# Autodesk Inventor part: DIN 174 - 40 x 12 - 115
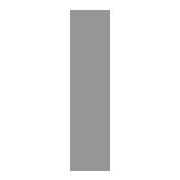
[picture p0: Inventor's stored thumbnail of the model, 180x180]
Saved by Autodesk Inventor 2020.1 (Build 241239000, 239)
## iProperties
IsCustomPart: 1
_CCFamilyMember: 175
_CCFamilyDisplayName: DIN EN 10278 - Flachstahl
_FrameMemberDoc: Frame Member File
_Version: 15.0.0
_GetPNFromCC: 1
Created: 2019-01
Part Number: DIN 174 - 40 x 12 - 115
Material: Stahl, weich
Description: Flachstahl
Document SubType Name: Modeling
Standard: DIN
Designer: lutzd
Standards Organization: DIN
Language: de-DE
Size Designation: 40 x 12
Categories: <MemberInstance><Categories><Category DisplayName="Profile" InternalName="089c4875-fa83-4c05-b084-43b9cc11f5ed" Mnemonic="GRDR"><CategoryParameter DisplayName="
Stock Number: 40 x 12
Mass: 406.353 g
Surface Area: 133.653 cm^2
Volume: 51.7647 cm^3
Density: 7.85 g/cm^3
Appearance: Semi-Polished(8)
G_L: 115,000 mm
G_W: 12,000 mm
G_H: 40,000 mm
DocNumber: ADSK-014318
Folder: .
Dimensions: 12x40x115 mm
Mass: 0,406 kg
Title: Profil-Bauteil
Author: lutzd
Revision Number: -
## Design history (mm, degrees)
node "Startebene"
node "Endebene"
sketch "Skizze"
  geometry: L1 (6, -20)-(-6, -20); L2 (-6, -20)-(-6, 20); L3 (-6, 20)-(6, 20); L4 (6, 20)-(6, -20); L5 (-6, 0)-(8, 0); L6 (0, -30)-(0, 40); L7 (0, 54)-(0, -44) reference; L8 (-9.2, 0)-(13.2, 0) reference
  constraints: 12 end point, 2 collinear, 2 parallel, 1 horizontal, 1 perpendicular
  dimensions: "d0" = 40 distance between parallel lines of L3 L1 (= G_W); "d1" = 12 distance between parallel lines of L4 L2 (= G_H); "d4" = 6 distance between parallel lines of L6 L4 (= 0.5 x d1); "d5" = 20 distance between parallel lines of L5 L3 (= 0.5 x d0)
extrude "Körper" new body sketch "Skizze" stored distance "d2" = 115 (= G_L); taper "d3" = 0 deg
node "Driven Length"
  sketch "Sketch3"
    geometry: L1 (0, 0)-(10, 0) reference
    constraints: 2 end point, 1 horizontal
  workplane "Work Plane3"
  sketch "Sketch4"
    geometry: L1 (-2, 0)-(12, 0) reference; L2 (-2, 115)-(12, 115) reference
    dimensions: "d9" = 115 distance between parallel lines of L1 L2 (derived)
sketch "Skizze5"
  geometry: L1 (16.5, -20)-(98.5, -20); L2 (0, 0)-(115, 0) reference; L3 (0, -40)-(0, 0) reference; 6 further points
  constraints: 3 midpoint, 2 coincident, 2 end point, 1 horizontal, 1 horizontal alignment, 1 vertical alignment
  dimensions: "d10" = 82 distance of L1.start L1.end
hole "Bohrung1" sketch "Skizze5" at (16.5, -20), (98.5, -20) diameter "d12" = 13.5; stored, may be unused: countersink angle "d16" = 90 deg, drill point angle "d18" = 118 deg; dims "d13" = 16, "d14" = 20, "d15" = 13, "d17" = 8
body "Solid1"
other parameters: "G_W" = 40 [user parameter; used in 1 equation term], "G_H" = 12 [user parameter; used in 1 equation term], "G_L" = 115 (= d9) [user parameter; used in 1 equation term], "G_OFFSET_START" = 0 [user parameter; used in 1 equation term], "G_OFFSET_END" = 0 [user parameter; used in 1 equation term], "d6" = 0 (computed from G_OFFSET_START), "d7" = 115 (= G_OFFSET_END + B_L), "B_L" = 115 [user parameter; used in 1 equation term], "d8" = 90 deg
